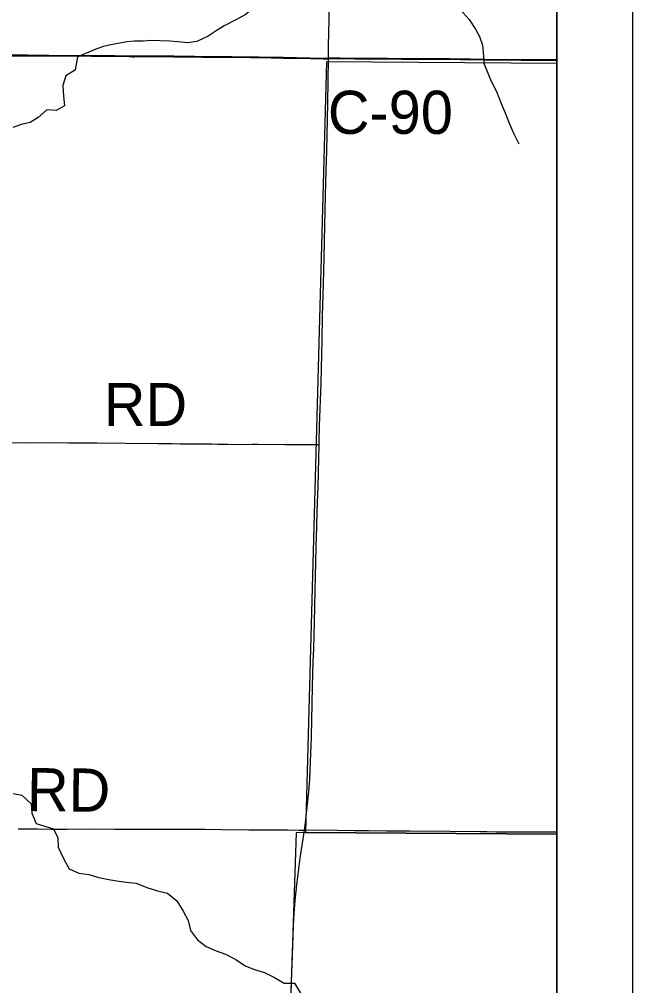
# Model space of a CAD drawing. Extents: x -11.1 to 34, y -3.9 to 22.
# Drawn here: x 8.192 to 9, y 18.032 to 19.305 of the extents above; entities that cross this region are included whole.
import ezdxf

# ---------------------------------------------------------------- set-up
doc = ezdxf.new("R2010")
doc.units = 0
for name, color, linetype in [('GM_X_Corporation', 7, 'Continuous'), ('GM_X_County_Road', 7, 'Continuous'), ('GM_X_County_Road_Text', 7, 'Continuous'), ('GM_X_Minor_River', 7, 'Continuous'), ('GM_X_State_Route', 7, 'Continuous'), ('GM_X_Township_Road', 7, 'Continuous'), ('GM_X_Township_Road_Text', 7, 'Continuous'), ('SH_Data', 7, 'Continuous')]:
    doc.layers.add(name, color=color, linetype=linetype)

msp = doc.modelspace()

# ---------------------------------------------------------------- linework, layer by layer
at = {"layer": 'GM_X_Corporation'}
for points in [[(8.1693, 19.2576), (8.2029, 19.2576), (8.2308, 19.2575), (8.3178, 19.2568), (8.3364, 19.2566), (8.3594, 19.2565), (8.3713, 19.2564), (8.3955, 19.2562), (8.4514, 19.2557), (8.4719, 19.2555), (8.4961, 19.2553), (8.5079, 19.2551), (8.5396, 19.2545), (8.5924, 19.2534), (8.5986, 19.2536), (8.6042, 19.2537), (8.6147, 19.2538), (8.6539, 19.2534), (8.6769, 19.2533), (8.7216, 19.2529), (8.7589, 19.2528), (8.7863, 19.2524), (8.8049, 19.2522), (8.8527, 19.2518), (8.8875, 19.2515), (8.9, 19.2515), (8.9, 20.9)], [(8.1693, 19.2576), (8.2029, 19.2576), (8.2308, 19.2575), (8.3178, 19.2568), (8.3364, 19.2566), (8.3594, 19.2565), (8.3713, 19.2564), (8.3955, 19.2562), (8.4514, 19.2557), (8.4719, 19.2555), (8.4961, 19.2553), (8.5079, 19.2551), (8.5396, 19.2545), (8.5924, 19.2534), (8.5986, 19.2536), (8.6042, 19.2537), (8.6147, 19.2538), (8.6539, 19.2534), (8.6769, 19.2533), (8.7216, 19.2529), (8.7589, 19.2528), (8.7863, 19.2524), (8.8049, 19.2522), (8.8527, 19.2518), (8.8875, 19.2515), (8.9, 19.2515), (8.9, 20.9)], [(8.9, 14.1), (8.9, 19.2515), (8.8875, 19.2515), (8.8527, 19.2518), (8.8049, 19.2522), (8.7863, 19.2524), (8.7589, 19.2528), (8.7216, 19.2529), (8.6769, 19.2533), (8.6539, 19.2534), (8.6147, 19.2538), (8.6042, 19.2537), (8.5986, 19.2536), (8.5924, 19.2534), (8.5396, 19.2545), (8.5079, 19.2551), (8.4961, 19.2553), (8.4719, 19.2555), (8.4514, 19.2557), (8.3955, 19.2562), (8.3713, 19.2564), (8.3594, 19.2565), (8.3364, 19.2566), (8.3178, 19.2568), (8.2308, 19.2575), (8.2029, 19.2576), (8.1693, 19.2576)], [(8.9, 15.2587), (8.9, 19.2515), (8.8875, 19.2515), (8.8527, 19.2518), (8.8049, 19.2522), (8.7863, 19.2524), (8.7589, 19.2528), (8.7216, 19.2529), (8.6769, 19.2533), (8.6539, 19.2534), (8.6147, 19.2538), (8.6042, 19.2537), (8.5986, 19.2536), (8.5924, 19.2534), (8.5396, 19.2545), (8.5079, 19.2551), (8.4961, 19.2553), (8.4719, 19.2555), (8.4514, 19.2557), (8.3955, 19.2562), (8.3713, 19.2564), (8.3594, 19.2565), (8.3364, 19.2566), (8.3178, 19.2568), (8.2308, 19.2575), (8.2029, 19.2576), (8.1693, 19.2576)]]:
    msp.add_lwpolyline(points, dxfattribs=at)
for points in [[(8.9, 18.2314), (8.9, 19.2468), (8.5967, 19.2489), (8.569, 18.2332)], [(8.9, 17.2929), (8.9, 18.2314), (8.569, 18.2332), (8.5569, 18.2331), (8.525, 17.2867)]]:
    msp.add_lwpolyline(points, close=True, dxfattribs=at)
at = {"layer": 'GM_X_County_Road'}
for points in [[(8.1695, 19.257), (8.2497, 19.2568), (8.287, 19.2565), (8.3181, 19.2562), (8.3367, 19.256), (8.3715, 19.2559), (8.3957, 19.2557), (8.433, 19.2553), (8.4516, 19.2552), (8.4721, 19.2549), (8.4964, 19.2547), (8.5082, 19.2545), (8.524, 19.2542), (8.5399, 19.2539), (8.5756, 19.2532), (8.5926, 19.2529), (8.5988, 19.253)], [(8.5988, 19.253), (8.6044, 19.2532), (8.615, 19.2533), (8.6336, 19.2531), (8.6541, 19.2528), (8.6958, 19.2526), (8.7088, 19.2525), (8.7219, 19.2523), (8.7728, 19.252), (8.7865, 19.2519), (8.8051, 19.2516), (8.8238, 19.2515), (8.853, 19.2513), (8.8704, 19.2511), (8.8878, 19.251), (8.9, 19.2509)]]:
    msp.add_lwpolyline(points, dxfattribs=at)
at = {"layer": 'GM_X_Minor_River'}
msp.add_line((8.2662, 19.2382), (8.269, 19.2556), dxfattribs=at)
for points in [[(8.5042, 19.3432), (8.5039, 19.3337), (8.4994, 19.319), (8.4897, 19.3109), (8.4762, 19.3037), (8.462, 19.2965), (8.4512, 19.2899), (8.4407, 19.2826), (8.4261, 19.2758), (8.4147, 19.2742), (8.4003, 19.2753), (8.3905, 19.2763), (8.3655, 19.2769), (8.3552, 19.2761), (8.3438, 19.276), (8.3336, 19.2751), (8.3126, 19.2715), (8.303, 19.2691), (8.2927, 19.2655), (8.269, 19.2554)], [(8.7729, 19.3178), (8.7847, 19.3049), (8.7931, 19.2922), (8.7981, 19.2822), (8.8024, 19.2707), (8.8035, 19.2562), (8.8038, 19.248)], [(8.3424, 19.2545), (8.3417, 19.2544)], [(8.8037, 19.2482), (8.8136, 19.2235), (8.8206, 19.2097), (8.8268, 19.194), (8.8319, 19.1817), (8.8374, 19.1683), (8.8436, 19.1541), (8.8502, 19.1407)], [(8.2662, 19.2382), (8.2535, 19.2305), (8.2494, 19.2176), (8.2503, 19.2039), (8.2516, 19.191), (8.2408, 19.1847), (8.2282, 19.1857), (8.2169, 19.1757), (8.2065, 19.169), (8.1965, 19.1669), (8.1835, 19.1622)], [(8.1842, 18.285), (8.1952, 18.2825), (8.2079, 18.2712), (8.2085, 18.2587), (8.2143, 18.2453), (8.2272, 18.2412), (8.2371, 18.2384), (8.243, 18.2265), (8.2431, 18.2139), (8.2505, 18.1993), (8.2579, 18.1855), (8.2703, 18.1796), (8.2837, 18.1782), (8.297, 18.1741), (8.3099, 18.1716), (8.3205, 18.1699), (8.3327, 18.1681), (8.346, 18.1667)], [(8.346, 18.1667), (8.3601, 18.1611), (8.3741, 18.1567), (8.3874, 18.1534), (8.3994, 18.1433), (8.408, 18.1298), (8.4146, 18.1175), (8.4174, 18.1041), (8.4267, 18.0918), (8.438, 18.0832), (8.4516, 18.0773), (8.4638, 18.0729), (8.4774, 18.0661), (8.4898, 18.0579), (8.5019, 18.0527), (8.5152, 18.0487), (8.5281, 18.0424), (8.5409, 18.0349), (8.5546, 18.035), (8.5624, 18.0216)]]:
    msp.add_lwpolyline(points, dxfattribs=at)
at = {"layer": 'GM_X_State_Route'}
for points in [[(8.6049, 19.5854), (8.6046, 19.5667), (8.6043, 19.5481), (8.6039, 19.5295), (8.6036, 19.5108), (8.6032, 19.4922), (8.6029, 19.4736), (8.6025, 19.4549), (8.6022, 19.4363), (8.6019, 19.4176), (8.6015, 19.399), (8.6012, 19.3804), (8.6008, 19.3617), (8.6005, 19.3431), (8.6001, 19.3245), (8.5998, 19.3058), (8.5995, 19.2872), (8.5991, 19.2701), (8.5988, 19.253)], [(8.5988, 19.253), (8.5986, 19.2242), (8.598, 19.1944), (8.5968, 19.1316), (8.596, 19.1061), (8.5949, 19.0726), (8.5938, 19.0129), (8.5932, 18.9906), (8.5922, 18.9564), (8.591, 18.9136), (8.5904, 18.8825), (8.5891, 18.8254), (8.5872, 18.7695), (8.5867, 18.7483), (8.5866, 18.7445), (8.5852, 18.6899), (8.5839, 18.6564), (8.5834, 18.6365), (8.5827, 18.6098), (8.5812, 18.552), (8.5803, 18.5104), (8.5794, 18.4756), (8.5789, 18.4589), (8.5778, 18.4259), (8.5766, 18.3595), (8.5748, 18.3154), (8.5742, 18.3036), (8.5729, 18.2869), (8.5704, 18.2628), (8.568, 18.2425), (8.5671, 18.2366), (8.5617, 18.1995), (8.5571, 18.1643), (8.555, 18.1439), (8.5536, 18.1265), (8.5527, 18.111), (8.5513, 18.0719), (8.5501, 18.0371), (8.5484, 17.9861)]]:
    msp.add_lwpolyline(points, dxfattribs=at)
at = {"layer": 'GM_X_Township_Road'}
for points in [[(8.1695, 19.257), (8.2497, 19.2568), (8.287, 19.2565), (8.3181, 19.2562), (8.3367, 19.256), (8.3715, 19.2559), (8.3957, 19.2557), (8.433, 19.2553), (8.4516, 19.2552), (8.4721, 19.2549), (8.4964, 19.2547), (8.5082, 19.2545), (8.524, 19.2542), (8.5399, 19.2539), (8.5756, 19.2532), (8.5926, 19.2529), (8.5988, 19.253)], [(8.1655, 18.7475), (8.1996, 18.7471), (8.2363, 18.7473), (8.2568, 18.7471), (8.2717, 18.7469), (8.294, 18.7467), (8.3319, 18.7463), (8.3748, 18.7462), (8.3934, 18.746), (8.404, 18.7457), (8.4245, 18.7454), (8.4462, 18.7454), (8.453, 18.7453), (8.4667, 18.745), (8.4772, 18.7449), (8.499, 18.7452), (8.5064, 18.7452), (8.5418, 18.7448), (8.5636, 18.7447), (8.5735, 18.7446), (8.5866, 18.7445)], [(8.1905, 18.2383), (8.216, 18.2381), (8.234, 18.2379), (8.2552, 18.2378), (8.2887, 18.2381), (8.3173, 18.2379), (8.3372, 18.238), (8.3757, 18.2378), (8.4105, 18.2377), (8.4366, 18.2376), (8.459, 18.2375), (8.4944, 18.237), (8.5192, 18.2368), (8.5453, 18.2367), (8.5609, 18.2366), (8.5671, 18.2366)], [(8.5671, 18.2366), (8.5826, 18.2368), (8.6112, 18.2364), (8.6335, 18.2362), (8.6522, 18.236), (8.6758, 18.2358), (8.7063, 18.2356), (8.759, 18.235), (8.7988, 18.2347), (8.8081, 18.2346), (8.8199, 18.2344), (8.8454, 18.2344), (8.8646, 18.2344), (8.8764, 18.2343), (8.9, 18.2341)]]:
    msp.add_lwpolyline(points, dxfattribs=at)
at = {"layer": 'SH_Data'}
for p, q in [((9, 21), (9, 14)), ((8.9, 20.9), (8.9, 14.1))]:
    msp.add_line(p, q, dxfattribs=at)

# ---------------------------------------------------------------- texts
at = {"layer": 'GM_X_County_Road_Text'}
msp.add_text('C-90', height=0.05682, rotation=0, dxfattribs=at).set_placement((8.5985, 19.154))
at = {"layer": 'GM_X_Township_Road_Text'}
for rotation, p in [(0, (8.3034, 18.7691)), (359.5026, (8.202, 18.2616))]:
    msp.add_text('RD', height=0.05682, rotation=rotation, dxfattribs=at).set_placement(p)

doc.saveas('drawing.dxf')
